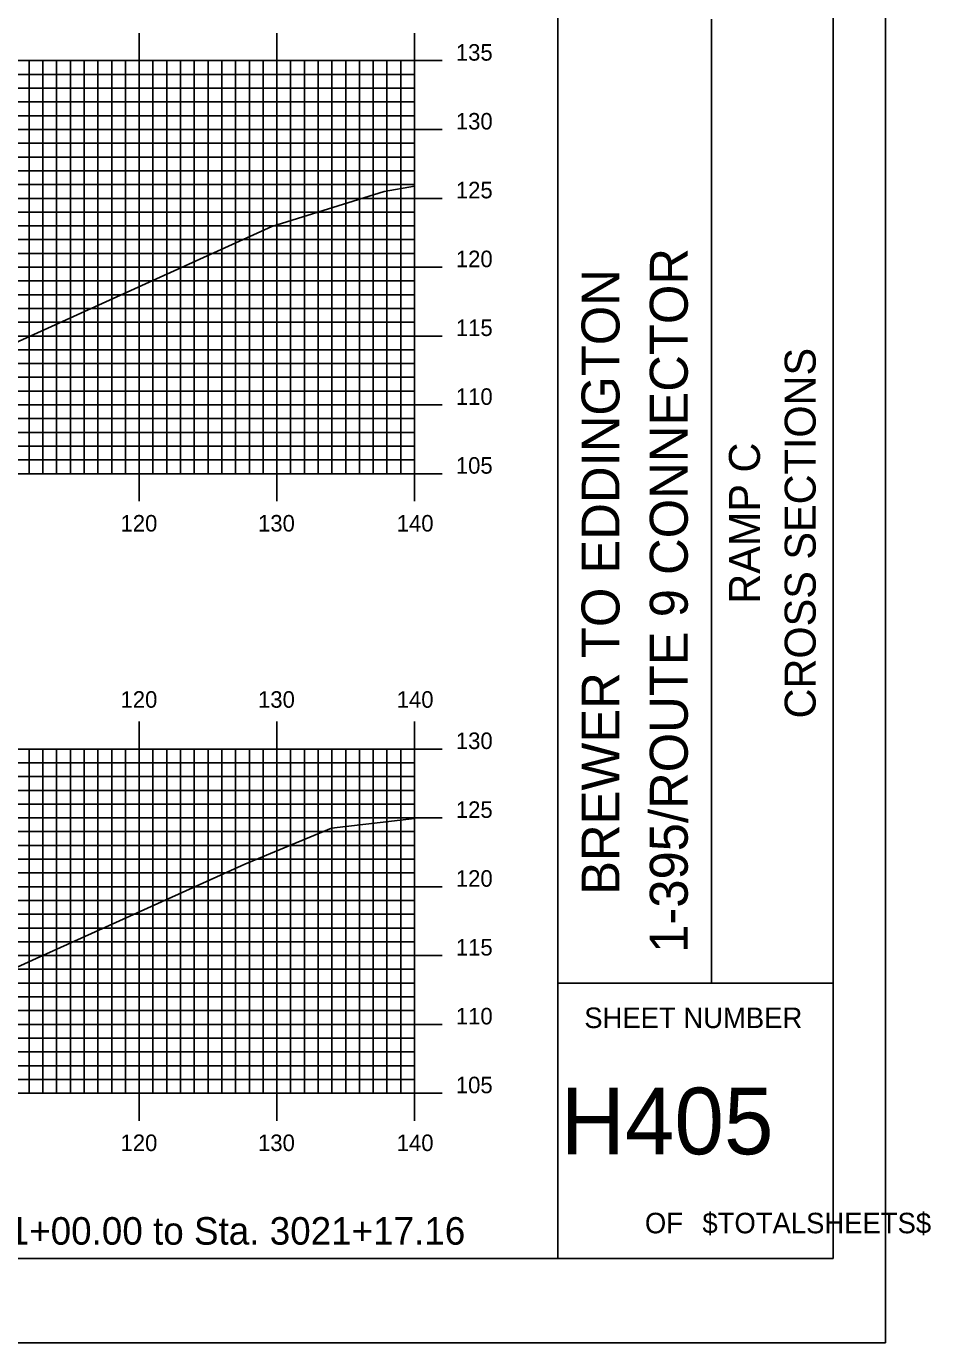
# Model space of a CAD drawing. Extents: x 1686373 to 1686716, y 461260 to 461480.
# Drawn here: x 1686650.6 to 1686716.3, y 461260 to 461355.6 of the extents above; entities that cross this region are included whole.
import ezdxf

# ---------------------------------------------------------------- set-up
doc = ezdxf.new("R2010")
doc.units = 0
for name, color, linetype in [('BORDER', 7, 'Continuous'), ('H_V ANNOTATION', 7, 'Continuous'), ('MAJOR', 7, 'Continuous'), ('MINOR', 7, 'Continuous'), ('PLOT BOUNDARY', 7, 'Continuous'), ('S_Roadway_Centerline', 7, 'Continuous')]:
    doc.layers.add(name, color=color, linetype=linetype)

msp = doc.modelspace()

# ---------------------------------------------------------------- linework, layer by layer
at = {"layer": 'BORDER'}
for p, q in [((1686689.169, 461266.072), (1686689.169, 461476.072)), ((1686700.351, 461286.078), (1686700.351, 461356.078)), ((1686689.169, 461286.078), (1686709.169, 461286.078))]:
    msp.add_line(p, q, dxfattribs=at)
msp.add_lwpolyline([(1686389.169, 461266.072), (1686709.169, 461266.072), (1686709.169, 461476.072), (1686389.169, 461476.072)], close=True, dxfattribs=at)
at = {"layer": 'MAJOR'}
for p, q in [((1686658.769, 461355.076), (1686658.769, 461353.072)), ((1686668.769, 461355.076), (1686668.769, 461353.072)), ((1686678.769, 461355.076), (1686678.769, 461353.072)), ((1686398.769, 461353.072), (1686678.769, 461353.072)), ((1686398.769, 461353.072), (1686678.769, 461353.072)), ((1686658.769, 461323.072), (1686658.769, 461353.072)), ((1686668.769, 461323.072), (1686668.769, 461353.072)), ((1686680.773, 461353.072), (1686676.765, 461353.072)), ((1686678.769, 461323.072), (1686678.769, 461353.072)), ((1686678.769, 461323.072), (1686678.769, 461353.072)), ((1686398.769, 461348.072), (1686678.769, 461348.072)), ((1686680.773, 461348.072), (1686676.765, 461348.072)), ((1686398.769, 461343.072), (1686678.769, 461343.072)), ((1686680.773, 461343.072), (1686676.765, 461343.072)), ((1686398.769, 461338.072), (1686678.769, 461338.072)), ((1686680.773, 461338.072), (1686676.765, 461338.072)), ((1686398.769, 461333.072), (1686678.769, 461333.072)), ((1686680.773, 461333.072), (1686676.765, 461333.072)), ((1686398.769, 461328.072), (1686678.769, 461328.072)), ((1686680.773, 461328.072), (1686676.765, 461328.072)), ((1686398.769, 461323.072), (1686678.769, 461323.072)), ((1686398.769, 461323.072), (1686678.769, 461323.072)), ((1686658.769, 461321.068), (1686658.769, 461323.072)), ((1686668.769, 461321.068), (1686668.769, 461323.072)), ((1686680.773, 461323.072), (1686676.765, 461323.072)), ((1686678.769, 461321.068), (1686678.769, 461323.072)), ((1686658.769, 461305.076), (1686658.769, 461303.072)), ((1686668.769, 461305.076), (1686668.769, 461303.072)), ((1686678.769, 461305.076), (1686678.769, 461303.072)), ((1686398.769, 461303.072), (1686678.769, 461303.072)), ((1686398.769, 461303.072), (1686678.769, 461303.072)), ((1686658.769, 461278.072), (1686658.769, 461303.072)), ((1686668.769, 461278.072), (1686668.769, 461303.072)), ((1686680.773, 461303.072), (1686676.765, 461303.072)), ((1686678.769, 461278.072), (1686678.769, 461303.072)), ((1686678.769, 461278.072), (1686678.769, 461303.072)), ((1686398.769, 461298.072), (1686678.769, 461298.072)), ((1686680.773, 461298.072), (1686676.765, 461298.072)), ((1686398.769, 461293.072), (1686678.769, 461293.072)), ((1686680.773, 461293.072), (1686676.765, 461293.072)), ((1686398.769, 461288.072), (1686678.769, 461288.072)), ((1686680.773, 461288.072), (1686676.765, 461288.072)), ((1686398.769, 461283.072), (1686678.769, 461283.072)), ((1686680.773, 461283.072), (1686676.765, 461283.072)), ((1686398.769, 461278.072), (1686678.769, 461278.072)), ((1686398.769, 461278.072), (1686678.769, 461278.072)), ((1686658.769, 461276.068), (1686658.769, 461278.072)), ((1686668.769, 461276.068), (1686668.769, 461278.072)), ((1686680.773, 461278.072), (1686676.765, 461278.072)), ((1686678.769, 461276.068), (1686678.769, 461278.072))]:
    msp.add_line(p, q, dxfattribs=at)
at = {"layer": 'MINOR'}
for p, q in [((1686650.769, 461323.072), (1686650.769, 461353.072)), ((1686651.769, 461323.072), (1686651.769, 461353.072)), ((1686652.769, 461323.072), (1686652.769, 461353.072)), ((1686653.769, 461323.072), (1686653.769, 461353.072)), ((1686654.769, 461323.072), (1686654.769, 461353.072)), ((1686655.769, 461323.072), (1686655.769, 461353.072)), ((1686656.769, 461323.072), (1686656.769, 461353.072)), ((1686657.769, 461323.072), (1686657.769, 461353.072)), ((1686659.769, 461323.072), (1686659.769, 461353.072)), ((1686660.769, 461323.072), (1686660.769, 461353.072)), ((1686661.769, 461323.072), (1686661.769, 461353.072)), ((1686662.769, 461323.072), (1686662.769, 461353.072)), ((1686663.769, 461323.072), (1686663.769, 461353.072)), ((1686664.769, 461323.072), (1686664.769, 461353.072)), ((1686665.769, 461323.072), (1686665.769, 461353.072)), ((1686666.769, 461323.072), (1686666.769, 461353.072)), ((1686667.769, 461323.072), (1686667.769, 461353.072)), ((1686669.769, 461323.072), (1686669.769, 461353.072)), ((1686670.769, 461323.072), (1686670.769, 461353.072)), ((1686671.769, 461323.072), (1686671.769, 461353.072)), ((1686672.769, 461323.072), (1686672.769, 461353.072)), ((1686673.769, 461323.072), (1686673.769, 461353.072)), ((1686674.769, 461323.072), (1686674.769, 461353.072)), ((1686675.769, 461323.072), (1686675.769, 461353.072)), ((1686676.769, 461323.072), (1686676.769, 461353.072)), ((1686677.769, 461323.072), (1686677.769, 461353.072)), ((1686398.769, 461352.072), (1686678.769, 461352.072)), ((1686678.769, 461352.072), (1686676.765, 461352.072)), ((1686398.769, 461351.072), (1686678.769, 461351.072)), ((1686678.769, 461351.072), (1686676.765, 461351.072)), ((1686398.769, 461350.072), (1686678.769, 461350.072)), ((1686678.769, 461350.072), (1686676.765, 461350.072)), ((1686398.769, 461349.072), (1686678.769, 461349.072)), ((1686678.769, 461349.072), (1686676.765, 461349.072)), ((1686398.769, 461347.072), (1686678.769, 461347.072)), ((1686678.769, 461347.072), (1686676.765, 461347.072)), ((1686398.769, 461346.072), (1686678.769, 461346.072)), ((1686678.769, 461346.072), (1686676.765, 461346.072)), ((1686398.769, 461345.072), (1686678.769, 461345.072)), ((1686678.769, 461345.072), (1686676.765, 461345.072)), ((1686398.769, 461344.072), (1686678.769, 461344.072)), ((1686678.769, 461344.072), (1686676.765, 461344.072)), ((1686398.769, 461342.072), (1686678.769, 461342.072)), ((1686678.769, 461342.072), (1686676.765, 461342.072)), ((1686398.769, 461341.072), (1686678.769, 461341.072)), ((1686678.769, 461341.072), (1686676.765, 461341.072)), ((1686398.769, 461340.072), (1686678.769, 461340.072)), ((1686678.769, 461340.072), (1686676.765, 461340.072)), ((1686398.769, 461339.072), (1686678.769, 461339.072)), ((1686678.769, 461339.072), (1686676.765, 461339.072)), ((1686398.769, 461337.072), (1686678.769, 461337.072)), ((1686678.769, 461337.072), (1686676.765, 461337.072)), ((1686398.769, 461336.072), (1686678.769, 461336.072)), ((1686678.769, 461336.072), (1686676.765, 461336.072)), ((1686398.769, 461335.072), (1686678.769, 461335.072)), ((1686678.769, 461335.072), (1686676.765, 461335.072)), ((1686398.769, 461334.072), (1686678.769, 461334.072)), ((1686678.769, 461334.072), (1686676.765, 461334.072)), ((1686398.769, 461332.072), (1686678.769, 461332.072)), ((1686678.769, 461332.072), (1686676.765, 461332.072)), ((1686398.769, 461331.072), (1686678.769, 461331.072)), ((1686678.769, 461331.072), (1686676.765, 461331.072)), ((1686398.769, 461330.072), (1686678.769, 461330.072)), ((1686678.769, 461330.072), (1686676.765, 461330.072)), ((1686398.769, 461329.072), (1686678.769, 461329.072)), ((1686678.769, 461329.072), (1686676.765, 461329.072)), ((1686398.769, 461327.072), (1686678.769, 461327.072)), ((1686678.769, 461327.072), (1686676.765, 461327.072)), ((1686398.769, 461326.072), (1686678.769, 461326.072)), ((1686678.769, 461326.072), (1686676.765, 461326.072)), ((1686398.769, 461325.072), (1686678.769, 461325.072)), ((1686678.769, 461325.072), (1686676.765, 461325.072)), ((1686398.769, 461324.072), (1686678.769, 461324.072)), ((1686678.769, 461324.072), (1686676.765, 461324.072)), ((1686650.769, 461278.072), (1686650.769, 461303.072)), ((1686651.769, 461278.072), (1686651.769, 461303.072)), ((1686652.769, 461278.072), (1686652.769, 461303.072)), ((1686653.769, 461278.072), (1686653.769, 461303.072)), ((1686654.769, 461278.072), (1686654.769, 461303.072)), ((1686655.769, 461278.072), (1686655.769, 461303.072)), ((1686656.769, 461278.072), (1686656.769, 461303.072)), ((1686657.769, 461278.072), (1686657.769, 461303.072)), ((1686659.769, 461278.072), (1686659.769, 461303.072)), ((1686660.769, 461278.072), (1686660.769, 461303.072)), ((1686661.769, 461278.072), (1686661.769, 461303.072)), ((1686662.769, 461278.072), (1686662.769, 461303.072)), ((1686663.769, 461278.072), (1686663.769, 461303.072)), ((1686664.769, 461278.072), (1686664.769, 461303.072)), ((1686665.769, 461278.072), (1686665.769, 461303.072)), ((1686666.769, 461278.072), (1686666.769, 461303.072)), ((1686667.769, 461278.072), (1686667.769, 461303.072)), ((1686669.769, 461278.072), (1686669.769, 461303.072)), ((1686670.769, 461278.072), (1686670.769, 461303.072)), ((1686671.769, 461278.072), (1686671.769, 461303.072)), ((1686672.769, 461278.072), (1686672.769, 461303.072)), ((1686673.769, 461278.072), (1686673.769, 461303.072)), ((1686674.769, 461278.072), (1686674.769, 461303.072)), ((1686675.769, 461278.072), (1686675.769, 461303.072)), ((1686676.769, 461278.072), (1686676.769, 461303.072)), ((1686677.769, 461278.072), (1686677.769, 461303.072)), ((1686398.769, 461302.072), (1686678.769, 461302.072)), ((1686678.769, 461302.072), (1686676.765, 461302.072)), ((1686398.769, 461301.072), (1686678.769, 461301.072)), ((1686678.769, 461301.072), (1686676.765, 461301.072)), ((1686398.769, 461300.072), (1686678.769, 461300.072)), ((1686678.769, 461300.072), (1686676.765, 461300.072)), ((1686398.769, 461299.072), (1686678.769, 461299.072)), ((1686678.769, 461299.072), (1686676.765, 461299.072)), ((1686398.769, 461297.072), (1686678.769, 461297.072)), ((1686678.769, 461297.072), (1686676.765, 461297.072)), ((1686398.769, 461296.072), (1686678.769, 461296.072)), ((1686678.769, 461296.072), (1686676.765, 461296.072)), ((1686398.769, 461295.072), (1686678.769, 461295.072)), ((1686678.769, 461295.072), (1686676.765, 461295.072)), ((1686398.769, 461294.072), (1686678.769, 461294.072)), ((1686678.769, 461294.072), (1686676.765, 461294.072)), ((1686398.769, 461292.072), (1686678.769, 461292.072)), ((1686678.769, 461292.072), (1686676.765, 461292.072)), ((1686398.769, 461291.072), (1686678.769, 461291.072)), ((1686678.769, 461291.072), (1686676.765, 461291.072)), ((1686398.769, 461290.072), (1686678.769, 461290.072)), ((1686678.769, 461290.072), (1686676.765, 461290.072)), ((1686398.769, 461289.072), (1686678.769, 461289.072)), ((1686678.769, 461289.072), (1686676.765, 461289.072)), ((1686398.769, 461287.072), (1686678.769, 461287.072)), ((1686678.769, 461287.072), (1686676.765, 461287.072)), ((1686398.769, 461286.072), (1686678.769, 461286.072)), ((1686678.769, 461286.072), (1686676.765, 461286.072)), ((1686398.769, 461285.072), (1686678.769, 461285.072)), ((1686678.769, 461285.072), (1686676.765, 461285.072)), ((1686398.769, 461284.072), (1686678.769, 461284.072)), ((1686678.769, 461284.072), (1686676.765, 461284.072)), ((1686398.769, 461282.072), (1686678.769, 461282.072)), ((1686678.769, 461282.072), (1686676.765, 461282.072)), ((1686398.769, 461281.072), (1686678.769, 461281.072)), ((1686678.769, 461281.072), (1686676.765, 461281.072)), ((1686398.769, 461280.072), (1686678.769, 461280.072)), ((1686678.769, 461280.072), (1686676.765, 461280.072)), ((1686398.769, 461279.072), (1686678.769, 461279.072)), ((1686678.769, 461279.072), (1686676.765, 461279.072))]:
    msp.add_line(p, q, dxfattribs=at)
at = {"layer": 'PLOT BOUNDARY'}
msp.add_lwpolyline([(1686372.982, 461259.954), (1686712.982, 461259.954), (1686712.982, 461479.954), (1686372.982, 461479.954)], close=True, dxfattribs=at)
at = {"layer": 'S_Roadway_Centerline'}
for points in [[(1686647.415, 461331.5), (1686668.412, 461341.037), (1686676.552, 461343.564), (1686678.769, 461343.949)], [(1686648.131, 461286.436), (1686651.024, 461287.732), (1686666.452, 461294.712), (1686672.739, 461297.326), (1686678.769, 461298.033)]]:
    msp.add_lwpolyline(points, dxfattribs=at)

# ---------------------------------------------------------------- texts
at = {"layer": 'BORDER'}
for s, height, p in [('1-395/ROUTE 9 CONNECTOR', 2.75575, (1686698.618, 461288.272)), ('BREWER TO EDDINGTON', 2.75575, (1686693.657, 461292.481)), ('CROSS SECTIONS', 2.25, (1686707.91, 461305.294)), ('RAMP C', 2.25, (1686703.86, 461313.629))]:
    msp.add_text(s, height=height, rotation=90, dxfattribs=at).set_placement(p)
for s, height, p in [('SHEET NUMBER', 1.49054, (1686691.1, 461282.805)), ('H405', 4.8388, (1686689.379, 461273.637)), ('$TOTALSHEETS$', 1.49054, (1686699.682, 461267.898)), ('OF', 1.4905, (1686695.503, 461267.898))]:
    msp.add_text(s, height=height, dxfattribs=at).set_placement(p)
at = {"layer": 'H_V ANNOTATION'}
for s, height, p in [('135', 1.2, (1686681.769, 461353.072)), ('130', 1.2, (1686681.769, 461348.072)), ('125', 1.2, (1686681.769, 461343.072)), ('120', 1.2, (1686681.769, 461338.072)), ('115', 1.2, (1686681.769, 461333.072)), ('110', 1.2, (1686681.769, 461328.072)), ('105', 1.2, (1686681.769, 461323.072)), ('120', 1.2, (1686657.409, 461318.872)), ('130', 1.2, (1686667.399, 461318.872)), ('140', 1.2, (1686677.474, 461318.872)), ('120', 1.2, (1686657.409, 461306.072)), ('130', 1.2, (1686667.399, 461306.072)), ('140', 1.2, (1686677.474, 461306.072)), ('130', 1.2, (1686681.769, 461303.072)), ('125', 1.2, (1686681.769, 461298.072)), ('120', 1.2, (1686681.769, 461293.072)), ('115', 1.2, (1686681.769, 461288.072)), ('110', 1.2, (1686681.769, 461283.072)), ('105', 1.2, (1686681.769, 461278.072)), ('120', 1.2, (1686657.409, 461273.872)), ('130', 1.2, (1686667.399, 461273.872)), ('140', 1.2, (1686677.474, 461273.872)), ('Sta. 3021+00.00 to Sta. 3021+17.16', 2.0004, (1686639.321, 461267.072))]:
    msp.add_text(s, height=height, dxfattribs=at).set_placement(p)

doc.saveas('drawing.dxf')
